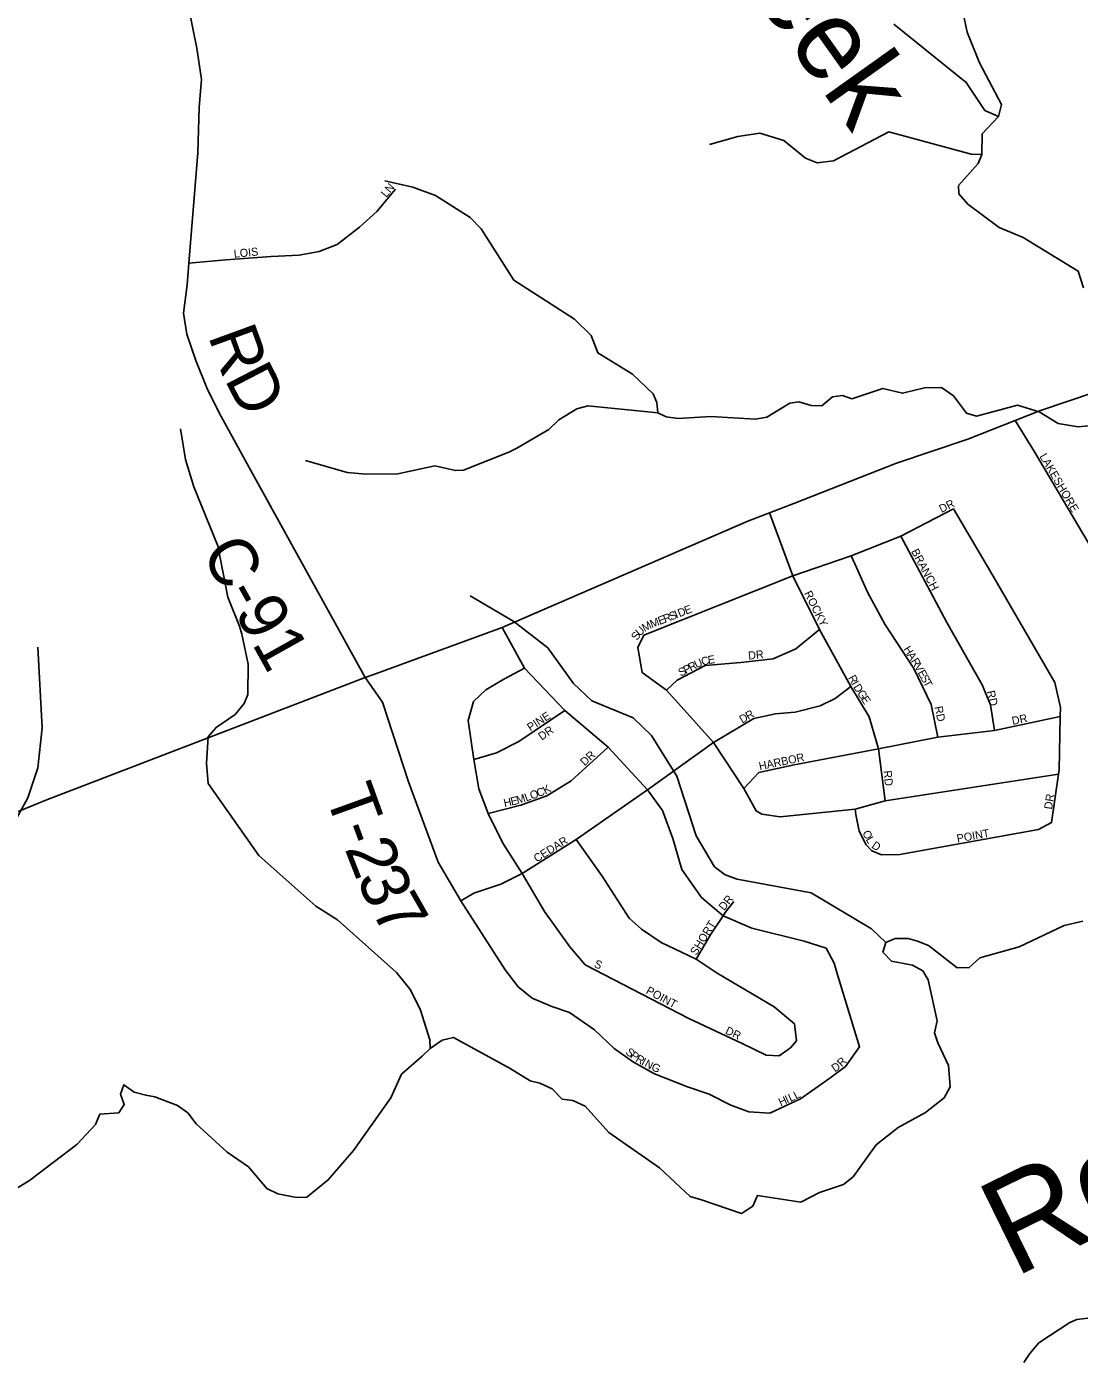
# Model space of a CAD drawing. Extents: x 1525783 to 1900577, y 218250 to 627376.
# Drawn here: x 1682109 to 1688647, y 431654 to 439896 of the extents above; entities that cross this region are included whole.
import ezdxf

# ---------------------------------------------------------------- set-up
doc = ezdxf.new("R2010")
doc.units = 0
for name, color, linetype in [('GM_X_County_Road', 7, 'Continuous'), ('GM_X_County_Road_Text', 7, 'Continuous'), ('GM_X_Major_Lake', 7, 'Continuous'), ('GM_X_Major_Lake_Text', 7, 'Continuous'), ('GM_X_Minor_River', 7, 'Continuous'), ('GM_X_Minor_River_Text', 7, 'Continuous'), ('GM_X_Township', 7, 'Continuous'), ('GM_X_Township_Road', 7, 'Continuous'), ('GM_X_Township_Road_Text', 7, 'Continuous'), ('GM_X_Township_Subdivision', 7, 'Continuous'), ('GM_X_Township_Subdivision_Text', 7, 'Continuous')]:
    doc.layers.add(name, color=color, linetype=linetype)

msp = doc.modelspace()

# ---------------------------------------------------------------- linework, layer by layer
at = {"layer": 'GM_X_County_Road'}
for points in [[(1684212.7, 435856.8), (1683491.3, 437159.5), (1683306, 437498.7), (1683228.3, 437653.3), (1683160.7, 437823.9), (1683105, 437986.4), (1683083.4, 438116.8), (1683106, 438293.2), (1683116.9, 438428.4), (1683172.5, 439113.2), (1683181.3, 439396), (1683195.9, 439568.4), (1683166.4, 439763), (1682982.8, 440669.9), (1682942.3, 441230.7), (1682863.3, 441583.8), (1682576.5, 442399.2), (1682191, 443523.6), (1682115.8, 443740.6), (1682111.7, 443844.7), (1682118.3, 444104), (1682123.2, 444246)], [(1684258.4, 435873.5), (1685061.4, 436166), (1686588.5, 436826.7), (1686722.3, 436878.2), (1686872.7, 436936), (1687511.7, 437185.9), (1687952.9, 437335.6), (1688247.6, 437451.6), (1688404.4, 437513.3), (1689227.7, 437790.2), (1689382.5, 437849.2), (1689466, 437891), (1689559.4, 437954.9), (1689620.8, 437996.6), (1689692.1, 438045.8), (1689741.2, 438082.6), (1689979.6, 438188.3), (1690065.6, 438217.8)], [(1679926.8, 434943.9), (1679927.7, 434944.2), (1680053, 434978.5), (1680263.4, 434996.1), (1680447.7, 434969.7), (1680605.7, 434879.2), (1680733.7, 434802.8), (1680947.9, 434736.2), (1681146.1, 434729.8), (1681408.7, 434759.4), (1682229.1, 435094.7), (1684212.7, 435856.8), (1684258.4, 435873.5)]]:
    msp.add_lwpolyline(points, dxfattribs=at)
at = {"layer": 'GM_X_Major_Lake'}
for points in [[(1688667.7, 434343.5), (1688552.9, 434317.5), (1688271.7, 434184.2), (1688027.8, 434116.4), (1687962.5, 434055.4), (1687888.3, 434054.7), (1687710.5, 434192.2), (1687640.8, 434219.6), (1687583, 434236.6), (1687502.8, 434236.1), (1687444.2, 434211), (1687427, 434151.2), (1687480.1, 434096.1), (1687609.9, 434069.7), (1687675.4, 434034.5), (1687708.5, 433979.7), (1687763.9, 433724.1), (1687746.4, 433650.2), (1687767.3, 433587.6), (1687834.9, 433448.1), (1687844.4, 433315.6), (1687807, 433246), (1687691, 433155.9), (1687520.9, 433062.7), (1687384.5, 432954.8), (1687242.5, 432756.8), (1687181.5, 432709.8), (1687032.2, 432660.3), (1686916.8, 432600.2), (1686646.9, 432641.2), (1686619.6, 432575.5), (1686548.5, 432528.6), (1686299.5, 432613.3), (1686229.7, 432634.6), (1686038.6, 432812.5), (1685723.9, 433032.7), (1685578.6, 433195.8), (1685501.1, 433231.3), (1685435, 433238.5), (1685372.1, 433301.8), (1685296.5, 433337.2), (1685236.7, 433352.3), (1685111.8, 433428.8)], [(1681873.4, 432578.7), (1682128.4, 432732.8), (1682420.8, 432956.4), (1682537.1, 433080.7), (1682564.4, 433146.4), (1682682.6, 433154.4), (1682715.6, 433206), (1682692.7, 433270.5), (1682713.8, 433328.3), (1682777, 433281.1), (1682850.8, 433263.8), (1682906.6, 433252.9), (1683045.8, 433198.4), (1683111.1, 433153.1), (1683161.9, 433086.1), (1683354.9, 432910.4), (1683487.4, 432817.9), (1683601.1, 432683.6), (1683668.6, 432650.4), (1683786.3, 432628.4), (1683850.4, 432631.3), (1683982.5, 432737.3), (1684139.9, 432919.1), (1684370.1, 433246), (1684436.8, 433393.2), (1684564.9, 433505.3), (1684615.9, 433552.6), (1684690.9, 433605.4), (1684759.3, 433622.3), (1685111.8, 433428.8)], [(1681873.4, 432578.7), (1682128.4, 432732.8), (1682420.8, 432956.4), (1682537.1, 433080.7), (1682564.4, 433146.4), (1682682.6, 433154.4), (1682715.6, 433206), (1682692.7, 433270.5), (1682713.8, 433328.3), (1682777, 433281.1), (1682850.8, 433263.8), (1682906.6, 433252.9), (1683045.8, 433198.4), (1683111.1, 433153.1), (1683161.9, 433086.1), (1683354.9, 432910.4), (1683487.4, 432817.9), (1683601.1, 432683.6), (1683668.6, 432650.4), (1683786.3, 432628.4), (1683850.4, 432631.3), (1683982.5, 432737.3), (1684139.9, 432919.1), (1684370.1, 433246), (1684436.8, 433393.2), (1684564.9, 433505.3), (1684615.9, 433552.6), (1684690.9, 433605.4), (1684759.3, 433622.3), (1685111.8, 433428.8)]]:
    msp.add_lwpolyline(points, dxfattribs=at)
at = {"layer": 'GM_X_Minor_River'}
for points in [[(1688673, 438273.8), (1688638.8, 438378.6), (1688297.9, 438587.3), (1688148.6, 438648.1), (1687954.9, 438794), (1687897.9, 438857.1), (1687896.9, 438909.3), (1688017.7, 439045.5), (1688040.8, 439101.2), (1688043.2, 439229.6), (1688143.5, 439338.1), (1688162.9, 439411.9), (1688025.4, 439671.1), (1687950.8, 439861), (1687923.1, 439989.8)], [(1688143.5, 439338.1), (1688060, 439375.7), (1687942.9, 439548.2), (1687494.6, 439911.2)], [(1688040.8, 439101.2), (1687974.7, 439104.5), (1687464, 439241.9), (1687119.8, 439063.6), (1687017.4, 439051.4), (1686945.7, 439078.8), (1686811.4, 439189.5), (1686661.9, 439234.3), (1686525.2, 439214.7), (1686349.8, 439163.6)], [(1685135.1, 438323.1), (1684931.7, 438639.8), (1684862.9, 438711.2), (1684649.2, 438847.2), (1684508, 438899.7), (1684334.5, 438938.8)], [(1688703.1, 437418.9), (1688638.8, 437412.1), (1688514.9, 437432.3), (1688395.9, 437504.6), (1688262.4, 437547.1), (1688008.5, 437477.5), (1687944.7, 437496.7), (1687864.5, 437604.4), (1687791.3, 437655.8), (1687685, 437653.7), (1687548, 437620.1), (1687426.2, 437650.3), (1687234.6, 437585.6), (1687174.8, 437606.7), (1687114.5, 437597.8), (1687047.3, 437542.8), (1686981.2, 437544), (1686905.4, 437567.4), (1686849.1, 437558.4), (1686705.2, 437472.7), (1686634.7, 437460), (1686358.4, 437477), (1686155.6, 437464.5), (1686081.6, 437473.9), (1686028, 437498.9), (1686023.2, 437563.2), (1686000.1, 437615.7), (1685872, 437738.4), (1685656, 437870.6), (1685615.9, 437979.6), (1685511.5, 438079.7), (1685135.1, 438323.1)], [(1686028, 437498.9), (1685593.7, 437542.8), (1685525.2, 437524), (1685413.6, 437455.8), (1685352.4, 437394.7), (1685153.7, 437280), (1685103.1, 437254.8)], [(1684615.9, 433552.6), (1684612.8, 433606.8), (1684556.1, 433790.2), (1684492.3, 433917.6), (1684406.1, 434025.3), (1684039.6, 434352.3), (1683905, 434436.8), (1683552.3, 434751.6), (1683236, 435198), (1683226.3, 435324.5), (1683237.2, 435486.7), (1683286.3, 435546), (1683403.9, 435626.2), (1683461.2, 435695.4), (1683484.2, 435751.2), (1683485.6, 435939.6), (1683444.9, 436124.8), (1683431.8, 436175.1), (1683358.9, 436354.8), (1683296.6, 436672.6), (1683147, 437040.1), (1683096, 437209.4), (1683065.4, 437398.4)], [(1685103.1, 437254.8), (1684822.7, 437143.9), (1684772.6, 437140.7), (1684645, 437169), (1684413.8, 437120.8), (1684217.6, 437118.1), (1684099.6, 437128.1), (1683840.7, 437202.7)], [(1685135.6, 436203.5), (1684862.7, 436363.3)], [(1687444.2, 434211), (1687355.5, 434294.9), (1686980.8, 434520.1), (1686521.2, 434604.6), (1686447.5, 434632), (1686380.3, 434681.3), (1686267.6, 434873.8), (1686146.2, 435242.9), (1685990.5, 435496.4), (1685876.3, 435604.7), (1685619.6, 435711.6), (1685505.3, 435817.9), (1685345.1, 436039.3), (1685135.6, 436203.5)], [(1681230, 432541.6), (1681348, 432866.4), (1681488, 433413.4), (1681511.3, 433591.4), (1681505.6, 434052.6), (1681569.5, 434380.4), (1681641, 434569.6), (1681684.4, 434647), (1681786.8, 434771.6), (1682036.5, 434961.8), (1682117.2, 435108.8), (1682178.6, 435296.2), (1682207.1, 435544.4), (1682180.1, 436044)]]:
    msp.add_lwpolyline(points, dxfattribs=at)
at = {"layer": 'GM_X_Township'}
for points in [[(1688302.6, 431604.5), (1688338.7, 431659.6), (1688395.2, 431726.1), (1688586.3, 431852.4), (1688631.1, 431871.1), (1688733.9, 431883.8), (1688781.7, 431876.2), (1688827.2, 431858.6), (1689063.5, 431567.3)], [(1689063.5, 431567.3), (1688827.2, 431858.6), (1688781.7, 431876.2), (1688733.9, 431883.8), (1688631.1, 431871.1), (1688586.3, 431852.4), (1688395.2, 431726.1), (1688338.7, 431659.6), (1688302.6, 431604.5)]]:
    msp.add_lwpolyline(points, dxfattribs=at)
at = {"layer": 'GM_X_Township_Road'}
msp.add_lwpolyline([(1684804.8, 434469.1), (1684664.3, 434709.1), (1684481.8, 435208.9), (1684319.2, 435702.1), (1684212.7, 435856.8)], dxfattribs=at)
at = {"layer": 'GM_X_Township_Subdivision'}
for points in [[(1683116.9, 438428.4), (1683346.5, 438448.7), (1683627.3, 438468.2), (1683801.8, 438476.6), (1683926.3, 438499.5), (1684037, 438544.6), (1684176.3, 438651.6), (1684283.5, 438748.9), (1684400.9, 438887.6)], [(1690369.5, 434926.2), (1690268.3, 434997.9), (1689993, 435160.9), (1689845.5, 435256.5), (1689701.9, 435348.1), (1689108.6, 436041.7), (1689027.2, 436140.7), (1688367.5, 437256.4), (1688247.6, 437451.6)], [(1688516.5, 435255.2), (1687439.9, 435090.7), (1687254.3, 435038.9), (1686788.5, 434991.8), (1686674.6, 435008.5), (1686639, 435027.4), (1686562.2, 435167.6), (1686375.2, 435451.5), (1686081.9, 435776.7), (1685932.2, 435886.6), (1685905.8, 436041.6), (1685941.8, 436119), (1686866.3, 436486.4), (1687229.6, 436612.1), (1687538.9, 436733.1), (1687865.5, 436901.9)], [(1687439.9, 435090.7), (1687398.6, 435413.3), (1687342.1, 435612.5), (1687228.3, 435799.7), (1687033.7, 436154.3), (1686866.3, 436486.4), (1686722.3, 436878.2)], [(1687254.3, 435038.9), (1687257.5, 435004.7), (1687279.1, 434902), (1687323.2, 434816.7), (1687358.4, 434779.7), (1687417.9, 434754.2), (1687532.1, 434757.6), (1688393.2, 434911.7), (1688474.4, 434955.9), (1688516.5, 435255.2), (1688520.2, 435281.8), (1688528.1, 435614.5), (1688529.4, 435670.7), (1688495, 435824), (1688096.6, 436509.3), (1687865.5, 436901.9)], [(1688119.4, 435527.9), (1688095.1, 435687), (1688041.9, 435810.6), (1687822.7, 436196.9), (1687538.9, 436733.1)], [(1687767.8, 435486.1), (1687726.5, 435687.6), (1687619.6, 435910.8), (1687437.9, 436187.9), (1687330.4, 436385), (1687261.9, 436539.1), (1687229.6, 436612.1)], [(1687141.1, 434025.1), (1687123.5, 434083.3), (1687073.6, 434176.7), (1686938.4, 434220), (1686611.8, 434300), (1686434.1, 434377.2), (1686299.7, 434489.9), (1686177.7, 434663.3), (1686122.2, 434857.1), (1686058.2, 435031.1), (1685964.5, 435157.8), (1685719.7, 435423.1), (1685451.4, 435651.1), (1685201.8, 435914.9), (1685061.4, 436166)], [(1686081.9, 435776.7), (1686149.5, 435839.3), (1686323.9, 435929.4), (1686544.7, 435948.3), (1686745.6, 435971.6), (1686885.3, 436034.5), (1687033.7, 436154.3)], [(1685201.8, 435914.9), (1685071.8, 435844.8), (1684960.1, 435779.2), (1684884.3, 435706.8), (1684851.4, 435589.3), (1684887.2, 435346.6), (1684917.5, 435164.5), (1684976.2, 435011.6), (1684983.5, 434992.4), (1685071.6, 434821.8), (1685187.4, 434638.6), (1685326.1, 434402.6), (1685483.2, 434184.3), (1685578.6, 434071.7), (1686221.8, 433739.6), (1686552.7, 433583.3), (1686701.2, 433511.6), (1686783.2, 433507.6), (1686852.6, 433558.1), (1686889.7, 433601.4), (1686878.1, 433706), (1686752.4, 433811.2), (1686396.8, 434020.2), (1686266.6, 434107.6), (1686050.7, 434210.9), (1685928.5, 434294.1), (1685850, 434362.1), (1685683.9, 434622.8), (1685522.3, 434850.2)], [(1684804.8, 434469.1), (1684886.1, 434517.3), (1685053.7, 434573.5), (1685187.4, 434638.6), (1685522.3, 434850.2), (1685964.5, 435157.8), (1686375.2, 435451.5), (1686624.6, 435601.4), (1686759.5, 435630.3), (1686882, 435641.5), (1687037.1, 435679.9), (1687130.4, 435725.8), (1687228.3, 435799.7)], [(1684887.2, 435346.6), (1685026.9, 435388.5), (1685166.9, 435459.4), (1685451.4, 435651.1)], [(1686562.2, 435167.6), (1686656.7, 435265.7), (1686876.3, 435314.6), (1687398.6, 435413.3), (1687767.8, 435486.1), (1688119.4, 435527.9), (1688528.1, 435614.5)], [(1684976.2, 435011.6), (1685177.5, 435064), (1685339.1, 435122.4), (1685491.6, 435215), (1685719.7, 435423.1)], [(1684804.8, 434469.1), (1685081.1, 434041.4), (1685162.7, 433935.1), (1685249.2, 433864.9), (1685370.2, 433813.9), (1685479.5, 433777.2), (1685635.2, 433669.2), (1685758.7, 433554), (1685878.8, 433468.9), (1686007.3, 433395.6), (1686213.8, 433314.5), (1686346.9, 433269.2), (1686481.5, 433201.8), (1686594.7, 433161), (1686724.7, 433152), (1686915.1, 433239.7), (1687096.5, 433369.8), (1687194.4, 433441.7), (1687281.4, 433564), (1687141.1, 434025.1)], [(1686266.6, 434107.6), (1686358.4, 434261.8), (1686434.1, 434377.2), (1686447.8, 434398.1), (1686500, 434466.2)]]:
    msp.add_lwpolyline(points, dxfattribs=at)

# ---------------------------------------------------------------- texts
at = {"layer": 'GM_X_County_Road_Text'}
for s, rotation, p in [('R', 290.06314, (1683234.5, 437976.7)), ('D', 297.33596, (1683335.5, 437707.8)), ('C-91', 299.18895, (1683190.4, 436631.3))]:
    msp.add_text(s, height=300, rotation=rotation, dxfattribs=at).set_placement(p)
at = {"layer": 'GM_X_Major_Lake_Text'}
msp.add_text('Rocky', height=600.01, rotation=26.1349, dxfattribs=at).set_placement((1688241.4, 432128.6))
at = {"layer": 'GM_X_Minor_River_Text'}
msp.add_text('Creek', height=499.97, rotation=305.44649, dxfattribs=at).set_placement((1686202.2, 440683.5))
at = {"layer": 'GM_X_Township_Road_Text'}
for s, rotation, p in [('T', 289.84179, (1683960.8, 435129.4)), ('-', 290.18045, (1684037.7, 434916.5)), ('2', 291.31409, (1684082.4, 434794.8)), ('3', 293.89356, (1684155.3, 434609)), ('7', 299.67298, (1684245, 434410.6))]:
    msp.add_text(s, height=300, rotation=rotation, dxfattribs=at).set_placement(p)
at = {"layer": 'GM_X_Township_Subdivision_Text'}
for s, rotation, p in [('LN', 49.39613, (1684342.3, 438832)), ('LOIS', 5.52416, (1683398.2, 438461.3)), ('LAKESHORE', 300.25682, (1688396.8, 437229)), ('DR', 26.55959, (1687790.5, 436876.3)), ('BRANCH', 297.89491, (1687600.6, 436639.1)), ('ROCKY', 296.56307, (1686936.3, 436379.3)), ('S', 21.40001, (1686110.4, 436209)), ('I', 21.40001, (1686143.2, 436221.9)), ('D', 21.40001, (1686163.7, 436229.9)), ('E', 21.40001, (1686204.7, 436246)), ('M', 28.75786, (1685946.8, 436137.8)), ('M', 21.40001, (1685991.6, 436162.5)), ('E', 21.40001, (1686040.8, 436181.8)), ('R', 21.40001, (1686073.5, 436194.6)), ('S', 58.18922, (1685901.2, 436082.2)), ('U', 43.47354, (1685917.7, 436109.5)), ('DR', 6.00541, (1686592.5, 435966.5)), ('H', 302.156, (1687551.8, 436032.5)), ('P', 27.82581, (1686202.7, 435876.8)), ('R', 27.82581, (1686233.8, 435893.2)), ('U', 23.98161, (1686268.1, 435911.3)), ('C', 16.29322, (1686306.6, 435928.6)), ('E', 8.60482, (1686342.9, 435939.3)), ('A', 302.156, (1687575.2, 435995.3)), ('R', 302.01311, (1687598.6, 435958)), ('V', 299.60662, (1687619.4, 435924.9)), ('S', 27.82581, (1686171.6, 435860.3)), ('R', 296.74967, (1687209.1, 435855.7)), ('E', 298.22676, (1687640.9, 435887)), ('S', 298.20268, (1687657.6, 435855.9)), ('I', 299.31829, (1687228.1, 435818.2)), ('D', 302.20933, (1687240.3, 435796.6)), ('G', 302.92425, (1687264.1, 435758.8)), ('T', 298.16569, (1687674.2, 435824.9)), ('RD', 283.21849, (1688071.1, 435769.1)), ('E', 302.89445, (1687288, 435721.9)), ('PINE', 33.18462, (1685237.6, 435520.4)), ('D', 30.87004, (1686553.4, 435569.1)), ('R', 30.17254, (1686591.1, 435591.6)), ('RD', 281.89272, (1687746.7, 435673)), ('DR', 11.88402, (1688232.8, 435561.5)), ('DR', 34.49867, (1685307.5, 435463.5)), ('DR', 42.8801, (1685575.1, 435304)), ('HARBOR', 11.88459, (1686662, 435279.9)), ('RD', 276.00542, (1687430, 435276.1)), ('K', 28.70173, (1685331.3, 435129.8)), ('H', 12.91762, (1685077.8, 435051.1)), ('E', 12.92294, (1685120.7, 435060.9)), ('M', 17.17628, (1685158.9, 435069.8)), ('L', 19.45041, (1685211.4, 435086.1)), ('O', 19.50976, (1685244.7, 435097.9)), ('C', 20.26257, (1685286.9, 435112.8)), ('DR', 81.03091, (1688476.2, 435034.6)), ('CEDAR', 32.00243, (1685277.3, 434706.7)), ('O', 297.33717, (1687297.2, 434891.9)), ('L', 299.92466, (1687318.6, 434850.7)), ('POINT', 10.00627, (1687889.8, 434831.2)), ('D', 324.72301, (1687351.9, 434802.8)), ('DR', 51.33663, (1686440.9, 434405.4)), ('SHORT', 58.39531, (1686268.7, 434127.2)), ('S', 336.78634, (1685629.2, 434060.6)), ('POINT', 331.92827, (1685951.1, 433897.4)), ('DR', 334.79826, (1686443.5, 433646.8)), ('S', 322.01002, (1685824.9, 433522.5)), ('P', 323.1434, (1685853.5, 433500.1)), ('R', 329.18482, (1685886.5, 433475.8)), ('I', 331.51416, (1685922.4, 433454.5)), ('N', 331.69765, (1685941.9, 433443.9)), ('G', 336.24342, (1685984.5, 433421.1)), ('D', 35.98237, (1687129.3, 433404)), ('R', 46.50049, (1687172.3, 433436.3)), ('H', 24.35531, (1686792.2, 433193.7)), ('I', 24.3354, (1686832.2, 433211.9)), ('L', 24.36259, (1686852.3, 433220.9)), ('L', 26.88429, (1686886.5, 433236.5))]:
    msp.add_text(s, height=50, rotation=rotation, dxfattribs=at).set_placement(p)

doc.saveas('drawing.dxf')
